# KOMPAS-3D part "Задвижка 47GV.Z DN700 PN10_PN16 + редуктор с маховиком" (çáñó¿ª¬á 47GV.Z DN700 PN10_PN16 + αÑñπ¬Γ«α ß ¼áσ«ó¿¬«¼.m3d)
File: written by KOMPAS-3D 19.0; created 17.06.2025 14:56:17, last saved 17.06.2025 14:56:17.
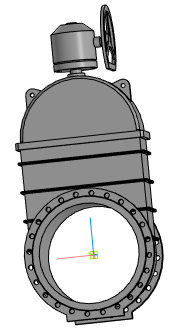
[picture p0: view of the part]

Document properties: Полное имя файла: Задвижка 47GV.Z DN700 PN10_PN16 + редуктор с маховиком.a3d

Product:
- Part/product: Задвижка 47GV.Z DN700 PN10_PN16 + редуктор с маховиком
    Масса: 2107.22

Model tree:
1. Операция без истории:1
